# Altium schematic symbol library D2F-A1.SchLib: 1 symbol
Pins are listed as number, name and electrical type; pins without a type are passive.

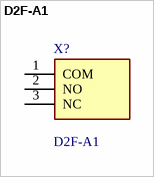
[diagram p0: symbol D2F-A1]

## D2F-A1
designator X?
SPDT-NO/NC Pin Plunger Microswitch, 3 A @ 125 V ac; Manufacturer_Name: Omron Electronics; Geometry.Height: 5.95mm
footprint D2FA1
pins: 1 COM, 2 NO, 3 NC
